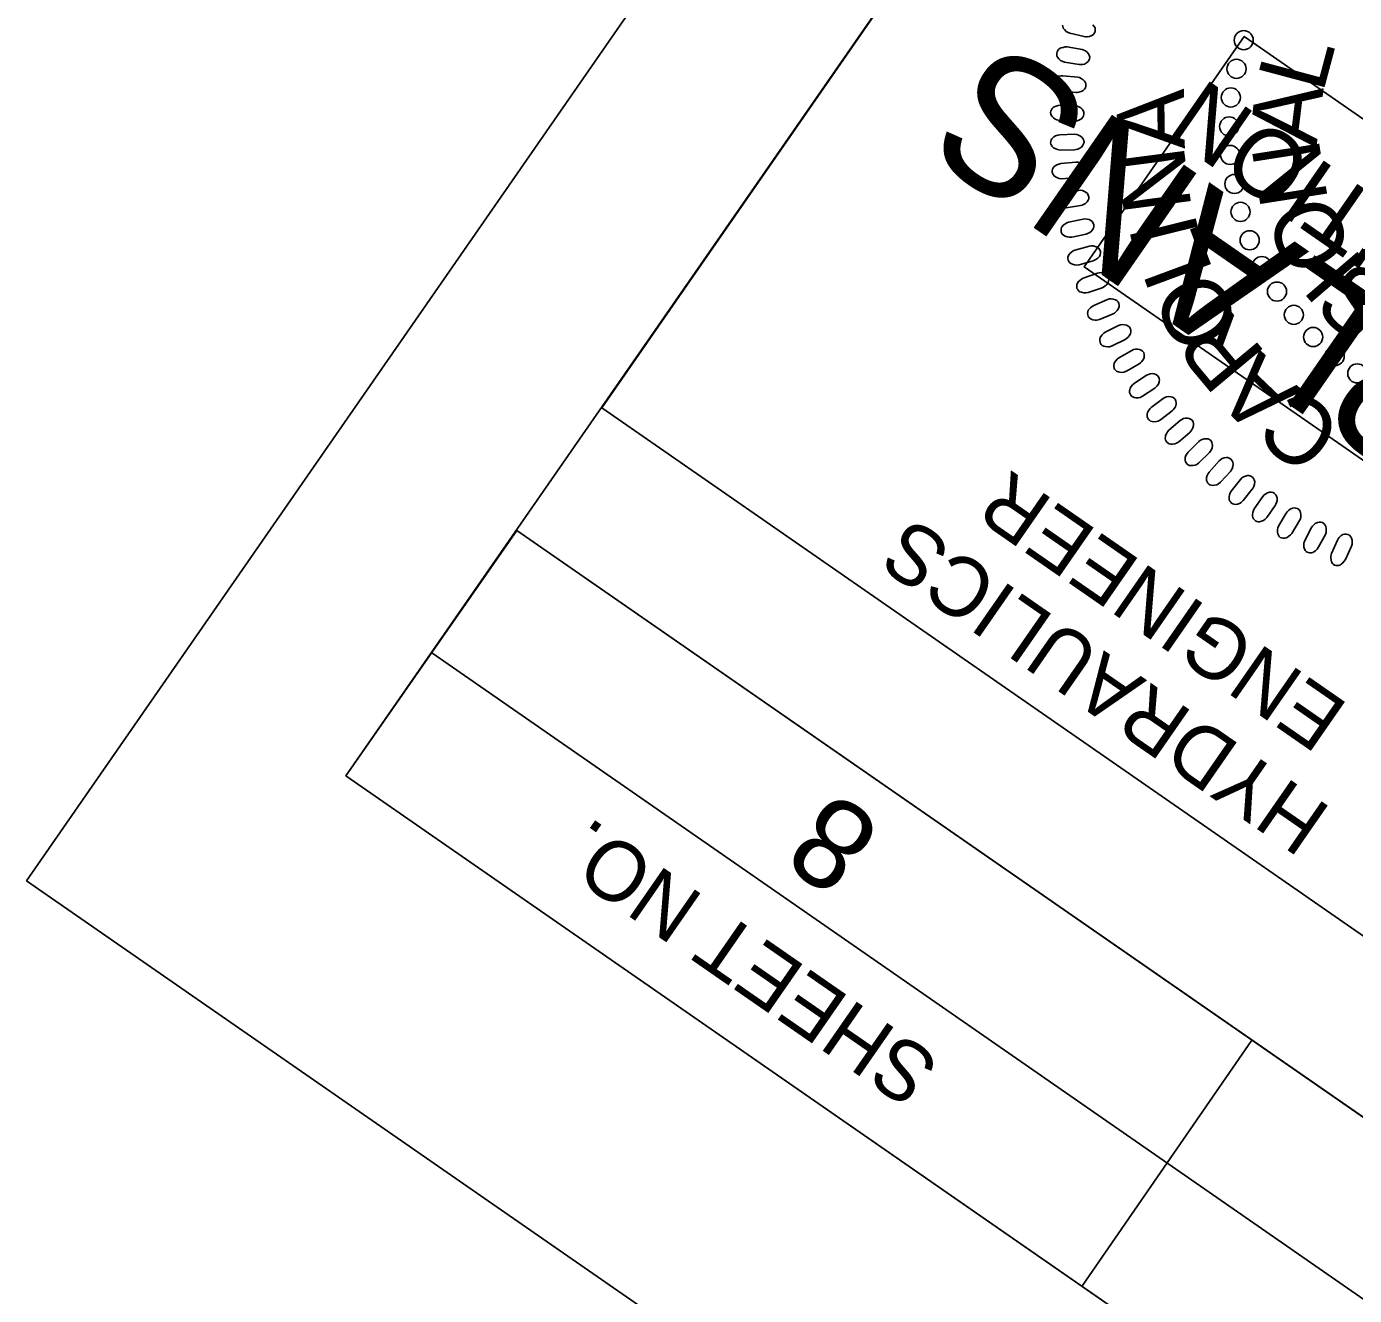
# Model space of a CAD drawing. Extents: x 478372 to 480379, y 492840 to 494699.
# Drawn here: x 478372.1 to 478483.3, y 493764.6 to 493871 of the extents above; entities that cross this region are included whole.
import ezdxf

# ---------------------------------------------------------------- set-up
doc = ezdxf.new("R2010")
doc.units = 0
for name, color, linetype in [('Sheet Data Field CELL', 7, 'Continuous'), ('Sheet PE Seal Cell', 7, 'Continuous'), ('Sheet Plan CELL', 7, 'Continuous'), ('Sheet Plot Border Outside CELL', 7, 'Continuous'), ('Sheet Sticker Incomplete CELL', 7, 'Continuous')]:
    doc.layers.add(name, color=color, linetype=linetype)

msp = doc.modelspace()

# ---------------------------------------------------------------- linework, layer by layer
at = {"layer": 'Sheet PE Seal Cell'}
msp.add_lwpolyline([(478461.42, 493871.09), (478461.53, 493870.95), (478461.59, 493870.84), (478461.61, 493870.67), (478461.6, 493870.52), (478461.52, 493870.39), (478461.45, 493870.29), (478461.32, 493870.19), (478461.13, 493870.12), (478460.94, 493870.09), (478460.81, 493870.09), (478460.68, 493870.11), (478459.48, 493870.39), (478459.28, 493870.47), (478459.16, 493870.55), (478459.02, 493870.7), (478458.93, 493870.82), (478458.88, 493870.95), (478458.86, 493871.06)], dxfattribs=at)
for points in [[(478460.25, 493867.77), (478459.04, 493867.98), (478458.83, 493868.05), (478458.7, 493868.12), (478458.55, 493868.26), (478458.46, 493868.38), (478458.4, 493868.5), (478458.38, 493868.61), (478458.38, 493868.73), (478458.42, 493868.83), (478458.47, 493868.95), (478458.54, 493869.04), (478458.66, 493869.13), (478458.75, 493869.17), (478458.91, 493869.21), (478459.09, 493869.24), (478459.26, 493869.24), (478460.5, 493869.04), (478460.66, 493868.98), (478460.79, 493868.92), (478460.93, 493868.8), (478461.05, 493868.67), (478461.11, 493868.56), (478461.15, 493868.39), (478461.14, 493868.24), (478461.08, 493868.1), (478461.01, 493868.01), (478460.89, 493867.9), (478460.7, 493867.81), (478460.52, 493867.77), (478460.38, 493867.77)], [(478459.97, 493865.43), (478458.75, 493865.56), (478458.54, 493865.62), (478458.41, 493865.68), (478458.25, 493865.81), (478458.15, 493865.92), (478458.08, 493866.04), (478458.06, 493866.15), (478458.05, 493866.26), (478458.08, 493866.37), (478458.12, 493866.49), (478458.19, 493866.59), (478458.3, 493866.68), (478458.39, 493866.73), (478458.54, 493866.78), (478458.73, 493866.82), (478458.89, 493866.83), (478460.14, 493866.71), (478460.3, 493866.67), (478460.44, 493866.61), (478460.59, 493866.5), (478460.71, 493866.38), (478460.78, 493866.27), (478460.83, 493866.11), (478460.83, 493865.96), (478460.78, 493865.81), (478460.72, 493865.71), (478460.6, 493865.6), (478460.42, 493865.5), (478460.24, 493865.45), (478460.1, 493865.43)], [(478459.84, 493863.03), (478458.62, 493863.08), (478458.4, 493863.12), (478458.26, 493863.18), (478458.1, 493863.3), (478457.99, 493863.4), (478457.92, 493863.52), (478457.88, 493863.62), (478457.87, 493863.74), (478457.89, 493863.85), (478457.93, 493863.97), (478457.99, 493864.07), (478458.09, 493864.17), (478458.18, 493864.23), (478458.33, 493864.29), (478458.51, 493864.34), (478458.67, 493864.35), (478459.93, 493864.31), (478460.09, 493864.28), (478460.23, 493864.23), (478460.39, 493864.13), (478460.52, 493864.02), (478460.6, 493863.92), (478460.65, 493863.76), (478460.66, 493863.61), (478460.62, 493863.46), (478460.56, 493863.36), (478460.46, 493863.23), (478460.29, 493863.12), (478460.1, 493863.06), (478459.97, 493863.04)], [(478459.88, 493860.63), (478458.66, 493860.6), (478458.44, 493860.64), (478458.3, 493860.69), (478458.12, 493860.79), (478458.01, 493860.89), (478457.93, 493861), (478457.89, 493861.1), (478457.87, 493861.21), (478457.88, 493861.33), (478457.91, 493861.45), (478457.97, 493861.55), (478458.07, 493861.66), (478458.15, 493861.72), (478458.29, 493861.79), (478458.47, 493861.86), (478458.63, 493861.88), (478459.89, 493861.92), (478460.06, 493861.9), (478460.2, 493861.86), (478460.36, 493861.77), (478460.5, 493861.66), (478460.58, 493861.56), (478460.65, 493861.41), (478460.67, 493861.26), (478460.63, 493861.11), (478460.58, 493861), (478460.49, 493860.87), (478460.32, 493860.75), (478460.14, 493860.68), (478460.01, 493860.65)], [(478460.05, 493858.3), (478458.82, 493858.2), (478458.6, 493858.22), (478458.46, 493858.26), (478458.28, 493858.35), (478458.16, 493858.44), (478458.07, 493858.55), (478458.02, 493858.65), (478457.99, 493858.76), (478458.01, 493858.87), (478458.03, 493858.99), (478458.08, 493859.1), (478458.17, 493859.21), (478458.24, 493859.28), (478458.38, 493859.36), (478458.56, 493859.43), (478458.72, 493859.47), (478459.97, 493859.58), (478460.14, 493859.58), (478460.28, 493859.54), (478460.45, 493859.47), (478460.6, 493859.37), (478460.68, 493859.28), (478460.76, 493859.13), (478460.79, 493858.98), (478460.76, 493858.83), (478460.72, 493858.72), (478460.63, 493858.58), (478460.47, 493858.45), (478460.3, 493858.37), (478460.17, 493858.33)], [(478460.37, 493855.95), (478459.16, 493855.77), (478458.94, 493855.77), (478458.79, 493855.8), (478458.61, 493855.89), (478458.49, 493855.97), (478458.39, 493856.07), (478458.34, 493856.17), (478458.3, 493856.27), (478458.3, 493856.39), (478458.31, 493856.51), (478458.36, 493856.62), (478458.44, 493856.74), (478458.51, 493856.81), (478458.65, 493856.9), (478458.82, 493856.99), (478458.97, 493857.03), (478460.22, 493857.22), (478460.39, 493857.23), (478460.53, 493857.2), (478460.7, 493857.14), (478460.86, 493857.05), (478460.95, 493856.96), (478461.03, 493856.81), (478461.07, 493856.67), (478461.06, 493856.52), (478461.02, 493856.41), (478460.94, 493856.26), (478460.79, 493856.12), (478460.62, 493856.03), (478460.5, 493855.98)], [(478460.84, 493853.56), (478459.64, 493853.31), (478459.42, 493853.3), (478459.27, 493853.32), (478459.08, 493853.39), (478458.96, 493853.46), (478458.85, 493853.56), (478458.79, 493853.65), (478458.75, 493853.76), (478458.75, 493853.87), (478458.75, 493853.99), (478458.79, 493854.11), (478458.86, 493854.23), (478458.93, 493854.31), (478459.06, 493854.4), (478459.22, 493854.5), (478459.38, 493854.56), (478460.6, 493854.82), (478460.77, 493854.84), (478460.92, 493854.82), (478461.09, 493854.77), (478461.25, 493854.69), (478461.35, 493854.61), (478461.44, 493854.47), (478461.5, 493854.33), (478461.49, 493854.17), (478461.46, 493854.06), (478461.39, 493853.91), (478461.25, 493853.76), (478461.09, 493853.66), (478460.97, 493853.6)], [(478461.44, 493851.31), (478460.25, 493850.98), (478460.03, 493850.95), (478459.88, 493850.97), (478459.69, 493851.03), (478459.56, 493851.09), (478459.45, 493851.18), (478459.39, 493851.27), (478459.34, 493851.37), (478459.32, 493851.48), (478459.32, 493851.61), (478459.35, 493851.72), (478459.42, 493851.85), (478459.48, 493851.93), (478459.61, 493852.04), (478459.76, 493852.14), (478459.91, 493852.21), (478461.12, 493852.55), (478461.29, 493852.58), (478461.43, 493852.57), (478461.61, 493852.53), (478461.78, 493852.46), (478461.88, 493852.39), (478461.98, 493852.25), (478462.04, 493852.11), (478462.04, 493851.96), (478462.02, 493851.84), (478461.96, 493851.69), (478461.83, 493851.53), (478461.67, 493851.42), (478461.56, 493851.36)], [(478462.18, 493849.06), (478461.03, 493848.66), (478460.81, 493848.62), (478460.66, 493848.63), (478460.46, 493848.68), (478460.33, 493848.73), (478460.21, 493848.81), (478460.14, 493848.9), (478460.08, 493849), (478460.07, 493849.11), (478460.06, 493849.23), (478460.08, 493849.35), (478460.14, 493849.48), (478460.19, 493849.56), (478460.31, 493849.68), (478460.46, 493849.79), (478460.61, 493849.87), (478461.79, 493850.29), (478461.96, 493850.32), (478462.1, 493850.33), (478462.28, 493850.29), (478462.45, 493850.23), (478462.56, 493850.17), (478462.67, 493850.04), (478462.74, 493849.9), (478462.75, 493849.75), (478462.73, 493849.64), (478462.68, 493849.48), (478462.56, 493849.31), (478462.41, 493849.19), (478462.3, 493849.12)], [(478463.1, 493846.88), (478461.97, 493846.4), (478461.75, 493846.35), (478461.61, 493846.34), (478461.41, 493846.38), (478461.27, 493846.43), (478461.15, 493846.5), (478461.07, 493846.58), (478461.01, 493846.68), (478460.99, 493846.79), (478460.97, 493846.91), (478460.98, 493847.03), (478461.03, 493847.17), (478461.08, 493847.25), (478461.2, 493847.37), (478461.34, 493847.5), (478461.48, 493847.58), (478462.63, 493848.07), (478462.8, 493848.12), (478462.94, 493848.13), (478463.12, 493848.11), (478463.3, 493848.06), (478463.41, 493848), (478463.52, 493847.88), (478463.6, 493847.75), (478463.62, 493847.6), (478463.62, 493847.48), (478463.57, 493847.33), (478463.46, 493847.15), (478463.32, 493847.02), (478463.22, 493846.94)], [(478464.12, 493844.73), (478463.02, 493844.18), (478462.81, 493844.12), (478462.66, 493844.1), (478462.46, 493844.13), (478462.32, 493844.17), (478462.19, 493844.23), (478462.11, 493844.31), (478462.04, 493844.4), (478462.01, 493844.51), (478461.99, 493844.63), (478461.99, 493844.75), (478462.03, 493844.89), (478462.08, 493844.98), (478462.18, 493845.1), (478462.32, 493845.24), (478462.45, 493845.33), (478463.57, 493845.9), (478463.73, 493845.95), (478463.88, 493845.97), (478464.06, 493845.96), (478464.24, 493845.93), (478464.35, 493845.87), (478464.48, 493845.76), (478464.56, 493845.63), (478464.59, 493845.48), (478464.59, 493845.37), (478464.56, 493845.21), (478464.46, 493845.03), (478464.33, 493844.89), (478464.23, 493844.8)], [(478465.28, 493842.69), (478464.22, 493842.07), (478464.01, 493841.99), (478463.87, 493841.97), (478463.66, 493841.98), (478463.52, 493842.01), (478463.4, 493842.07), (478463.31, 493842.14), (478463.23, 493842.23), (478463.2, 493842.33), (478463.16, 493842.45), (478463.16, 493842.57), (478463.2, 493842.71), (478463.23, 493842.8), (478463.33, 493842.94), (478463.46, 493843.08), (478463.58, 493843.18), (478464.67, 493843.81), (478464.82, 493843.88), (478464.97, 493843.91), (478465.15, 493843.91), (478465.33, 493843.89), (478465.45, 493843.84), (478465.58, 493843.74), (478465.67, 493843.62), (478465.71, 493843.47), (478465.72, 493843.35), (478465.7, 493843.19), (478465.61, 493843), (478465.49, 493842.85), (478465.39, 493842.76)], [(478466.59, 493840.64), (478465.57, 493839.96), (478465.37, 493839.87), (478465.22, 493839.84), (478465.02, 493839.84), (478464.87, 493839.86), (478464.75, 493839.91), (478464.66, 493839.97), (478464.58, 493840.05), (478464.53, 493840.16), (478464.49, 493840.27), (478464.48, 493840.39), (478464.51, 493840.54), (478464.54, 493840.63), (478464.63, 493840.77), (478464.74, 493840.92), (478464.86, 493841.03), (478465.91, 493841.73), (478466.06, 493841.8), (478466.2, 493841.84), (478466.38, 493841.86), (478466.56, 493841.84), (478466.68, 493841.8), (478466.82, 493841.71), (478466.92, 493841.59), (478466.97, 493841.45), (478466.98, 493841.33), (478466.97, 493841.17), (478466.9, 493840.98), (478466.78, 493840.82), (478466.69, 493840.73)], [(478468.05, 493838.74), (478467.07, 493837.99), (478466.88, 493837.89), (478466.73, 493837.85), (478466.53, 493837.83), (478466.39, 493837.85), (478466.25, 493837.89), (478466.16, 493837.95), (478466.07, 493838.02), (478466.02, 493838.12), (478465.97, 493838.24), (478465.96, 493838.36), (478465.97, 493838.5), (478466, 493838.6), (478466.08, 493838.74), (478466.19, 493838.9), (478466.3, 493839.01), (478467.3, 493839.78), (478467.45, 493839.86), (478467.58, 493839.91), (478467.76, 493839.94), (478467.94, 493839.93), (478468.07, 493839.9), (478468.21, 493839.81), (478468.32, 493839.71), (478468.37, 493839.56), (478468.4, 493839.45), (478468.4, 493839.29), (478468.33, 493839.09), (478468.23, 493838.93), (478468.14, 493838.83)], [(478469.54, 493836.94), (478468.62, 493836.14), (478468.43, 493836.03), (478468.29, 493835.97), (478468.08, 493835.95), (478467.94, 493835.95), (478467.8, 493835.98), (478467.71, 493836.03), (478467.62, 493836.11), (478467.56, 493836.2), (478467.5, 493836.31), (478467.48, 493836.43), (478467.49, 493836.58), (478467.51, 493836.67), (478467.58, 493836.82), (478467.67, 493836.99), (478467.78, 493837.11), (478468.73, 493837.93), (478468.87, 493838.03), (478469.01, 493838.09), (478469.18, 493838.12), (478469.36, 493838.13), (478469.49, 493838.11), (478469.64, 493838.03), (478469.75, 493837.93), (478469.82, 493837.79), (478469.85, 493837.68), (478469.85, 493837.52), (478469.8, 493837.31), (478469.71, 493837.15), (478469.63, 493837.04)], [(478471.17, 493835.24), (478470.29, 493834.38), (478470.11, 493834.25), (478469.97, 493834.19), (478469.77, 493834.15), (478469.63, 493834.15), (478469.49, 493834.17), (478469.39, 493834.22), (478469.3, 493834.28), (478469.23, 493834.38), (478469.17, 493834.48), (478469.14, 493834.6), (478469.14, 493834.75), (478469.15, 493834.84), (478469.21, 493835), (478469.3, 493835.17), (478469.4, 493835.29), (478470.29, 493836.18), (478470.43, 493836.28), (478470.56, 493836.35), (478470.74, 493836.39), (478470.91, 493836.41), (478471.04, 493836.4), (478471.19, 493836.33), (478471.31, 493836.24), (478471.39, 493836.1), (478471.42, 493835.99), (478471.44, 493835.83), (478471.4, 493835.63), (478471.32, 493835.45), (478471.25, 493835.34)], [(478472.93, 493833.67), (478472.11, 493832.76), (478471.93, 493832.62), (478471.8, 493832.55), (478471.6, 493832.5), (478471.46, 493832.48), (478471.32, 493832.5), (478471.22, 493832.54), (478471.12, 493832.6), (478471.05, 493832.69), (478470.98, 493832.79), (478470.94, 493832.91), (478470.93, 493833.05), (478470.94, 493833.15), (478470.99, 493833.31), (478471.07, 493833.48), (478471.16, 493833.61), (478471.99, 493834.55), (478472.12, 493834.66), (478472.25, 493834.74), (478472.42, 493834.8), (478472.6, 493834.82), (478472.72, 493834.82), (478472.88, 493834.76), (478473.01, 493834.67), (478473.09, 493834.54), (478473.13, 493834.44), (478473.16, 493834.28), (478473.14, 493834.07), (478473.07, 493833.89), (478473, 493833.78)], [(478474.77, 493832.18), (478474.01, 493831.22), (478473.84, 493831.07), (478473.71, 493830.99), (478473.52, 493830.93), (478473.38, 493830.9), (478473.24, 493830.91), (478473.13, 493830.94), (478473.03, 493831), (478472.96, 493831.08), (478472.88, 493831.18), (478472.84, 493831.29), (478472.82, 493831.44), (478472.82, 493831.54), (478472.86, 493831.69), (478472.92, 493831.87), (478473.01, 493832.01), (478473.78, 493833), (478473.9, 493833.12), (478474.02, 493833.2), (478474.19, 493833.27), (478474.37, 493833.31), (478474.49, 493833.31), (478474.65, 493833.26), (478474.78, 493833.19), (478474.88, 493833.06), (478474.93, 493832.96), (478474.97, 493832.8), (478474.95, 493832.59), (478474.9, 493832.41), (478474.84, 493832.29)], [(478476.69, 493830.81), (478475.99, 493829.81), (478475.84, 493829.65), (478475.71, 493829.56), (478475.53, 493829.49), (478475.38, 493829.45), (478475.25, 493829.45), (478475.14, 493829.48), (478475.03, 493829.52), (478474.95, 493829.6), (478474.87, 493829.7), (478474.82, 493829.81), (478474.79, 493829.95), (478474.79, 493830.05), (478474.82, 493830.21), (478474.87, 493830.39), (478474.94, 493830.53), (478475.65, 493831.57), (478475.77, 493831.7), (478475.89, 493831.79), (478476.05, 493831.87), (478476.22, 493831.92), (478476.35, 493831.93), (478476.51, 493831.89), (478476.64, 493831.82), (478476.74, 493831.7), (478476.8, 493831.6), (478476.85, 493831.45), (478476.85, 493831.24), (478476.8, 493831.05), (478476.75, 493830.93)], [(478477.61, 493830.18), (478476.98, 493829.14), (478476.9, 493828.93), (478476.87, 493828.78), (478476.88, 493828.58), (478476.9, 493828.43), (478476.96, 493828.31), (478477.03, 493828.22), (478477.11, 493828.14), (478477.22, 493828.1), (478477.34, 493828.07), (478477.46, 493828.06), (478477.6, 493828.1), (478477.69, 493828.13), (478477.83, 493828.23), (478477.97, 493828.35), (478478.07, 493828.47), (478478.73, 493829.55), (478478.8, 493829.7), (478478.83, 493829.84), (478478.84, 493830.03), (478478.81, 493830.2), (478478.77, 493830.32), (478478.67, 493830.46), (478478.55, 493830.55), (478478.4, 493830.59), (478478.29, 493830.6), (478478.13, 493830.59), (478477.94, 493830.5), (478477.79, 493830.38), (478477.69, 493830.29)], [(478479.73, 493828.96), (478479.17, 493827.87), (478479.1, 493827.66), (478479.08, 493827.51), (478479.1, 493827.31), (478479.14, 493827.17), (478479.2, 493827.05), (478479.27, 493826.96), (478479.36, 493826.89), (478479.47, 493826.86), (478479.59, 493826.83), (478479.71, 493826.84), (478479.85, 493826.88), (478479.94, 493826.92), (478480.07, 493827.02), (478480.2, 493827.15), (478480.3, 493827.28), (478480.89, 493828.39), (478480.95, 493828.55), (478480.97, 493828.7), (478480.96, 493828.88), (478480.93, 493829.06), (478480.88, 493829.17), (478480.77, 493829.3), (478480.65, 493829.39), (478480.49, 493829.42), (478480.38, 493829.42), (478480.22, 493829.39), (478480.04, 493829.3), (478479.89, 493829.17), (478479.81, 493829.07)], [(478481.9, 493827.91), (478481.4, 493826.79), (478481.35, 493826.57), (478481.34, 493826.42), (478481.37, 493826.22), (478481.41, 493826.08), (478481.48, 493825.96), (478481.56, 493825.88), (478481.66, 493825.82), (478481.77, 493825.79), (478481.89, 493825.77), (478482.01, 493825.78), (478482.15, 493825.83), (478482.23, 493825.88), (478482.36, 493825.99), (478482.48, 493826.13), (478482.57, 493826.27), (478483.09, 493827.41), (478483.13, 493827.58), (478483.15, 493827.72), (478483.13, 493827.9), (478483.09, 493828.08), (478483.03, 493828.19), (478482.91, 493828.31), (478482.78, 493828.39), (478482.63, 493828.41), (478482.51, 493828.41), (478482.36, 493828.37), (478482.18, 493828.26), (478482.05, 493828.13), (478481.97, 493828.02)]]:
    msp.add_lwpolyline(points, close=True, dxfattribs=at)
for centre in [(478474.05, 493869.81), (478473.45, 493867.41), (478472.97, 493865.01), (478472.83, 493862.58), (478472.92, 493860.19), (478473.27, 493857.76), (478473.78, 493855.42), (478474.55, 493853.04), (478475.57, 493850.88), (478476.84, 493848.74), (478478.25, 493846.79), (478479.87, 493844.93), (478481.68, 493843.34), (478483.57, 493841.88)]:
    msp.add_circle(centre, 0.801, dxfattribs=at)
at = {"layer": 'Sheet Plan CELL'}
for p, q in [((478577.51, 493714.73), (478413.13, 493828.72)), ((478577.51, 493714.73), (478413.13, 493828.72)), ((478570.37, 493704.42), (478406.01, 493818.45)), ((478460.54, 493765.43), (478474.74, 493786))]:
    msp.add_line(p, q, dxfattribs=at)
for points in [[(478398.82, 493808.16), (479631.35, 492953.18), (480229.82, 493815.92), (478997.32, 494670.89)], [(478502.42, 493782.01), (478420.26, 493838.99), (478484.38, 493931.45), (478566.55, 493874.46)], [(478563.21, 493694.11), (478398.82, 493808.16), (478413.13, 493828.72), (478577.51, 493714.73)]]:
    msp.add_lwpolyline(points, close=True, dxfattribs=at)
at = {"layer": 'Sheet Plot Border Outside CELL'}
msp.add_lwpolyline([(480379.45, 493739.53), (478996.18, 494699.08), (478372.06, 493799.36), (479755.33, 492839.81)], close=True, dxfattribs=at)
at = {"layer": 'Sheet Sticker Incomplete CELL'}
msp.add_lwpolyline([(478594.87, 493786.34), (478581.48, 493767.03), (478460.69, 493850.81), (478474.09, 493870.12)], close=True, dxfattribs=at)

# ---------------------------------------------------------------- texts
at = {"layer": 'Sheet Data Field CELL'}
msp.add_text('8', height=7.5, rotation=145.2516, dxfattribs=at).set_placement((478444.02, 493803.89))
at = {"layer": 'Sheet PE Seal Cell'}
for s, rotation, p in [('L', 75.0825, (478480.67, 493865.27)), ('A', 90.9244, (478469.12, 493860.71)), ('A', 83.0223, (478480.14, 493860.78)), ('N', 97.4138, (478469.69, 493855.71)), ('N', 98.9019, (478481.13, 493856.34)), ('O', 114.7814, (478483.35, 493851.99)), ('I', 103.9031, (478470.37, 493853.51)), ('L', 110.3925, (478471.52, 493850.46)), ('I', 130.661, (478484.49, 493851)), ('S', 138.6008, (478487.26, 493848.31)), ('O', 116.8819, (478473.97, 493845.68)), ('R', 129.8606, (478476.02, 493843.46)), ('A', 136.3499, (478479.03, 493840.41)), ('C', 142.8393, (478482.67, 493837.63))]:
    msp.add_text(s, height=5.67, rotation=rotation, dxfattribs=at).set_placement(p)
at = {"layer": 'Sheet Plan CELL'}
for s, p in [('ENGINEER', (478482.98, 493814.04)), ('HYDRAULICS', (478481.54, 493805.35)), ('SHEET NO.', (478448.81, 493784.23))]:
    msp.add_text(s, height=5, rotation=145.2516, dxfattribs=at).set_placement(p)
at = {"layer": 'Sheet Sticker Incomplete CELL'}
for s, height, p in [('INCOMPLETE PLANS', 11.52, (478580.85, 493781.82)), ('DO NOT USE FOR R/W ACQUISITION', 5.76, (478582.14, 493789.39))]:
    msp.add_text(s, height=height, rotation=145.2516, dxfattribs=at).set_placement(p)

doc.saveas('drawing.dxf')
